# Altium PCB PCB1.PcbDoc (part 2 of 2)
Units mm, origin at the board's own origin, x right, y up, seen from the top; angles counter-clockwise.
Board outline 100 x 100 mm, 4 copper layers (Top Layer, Layer 1, Layer 2, Bottom Layer), stack 1.55 mm thick; 90 components, 49 nets, 314 pads, 474 vias.
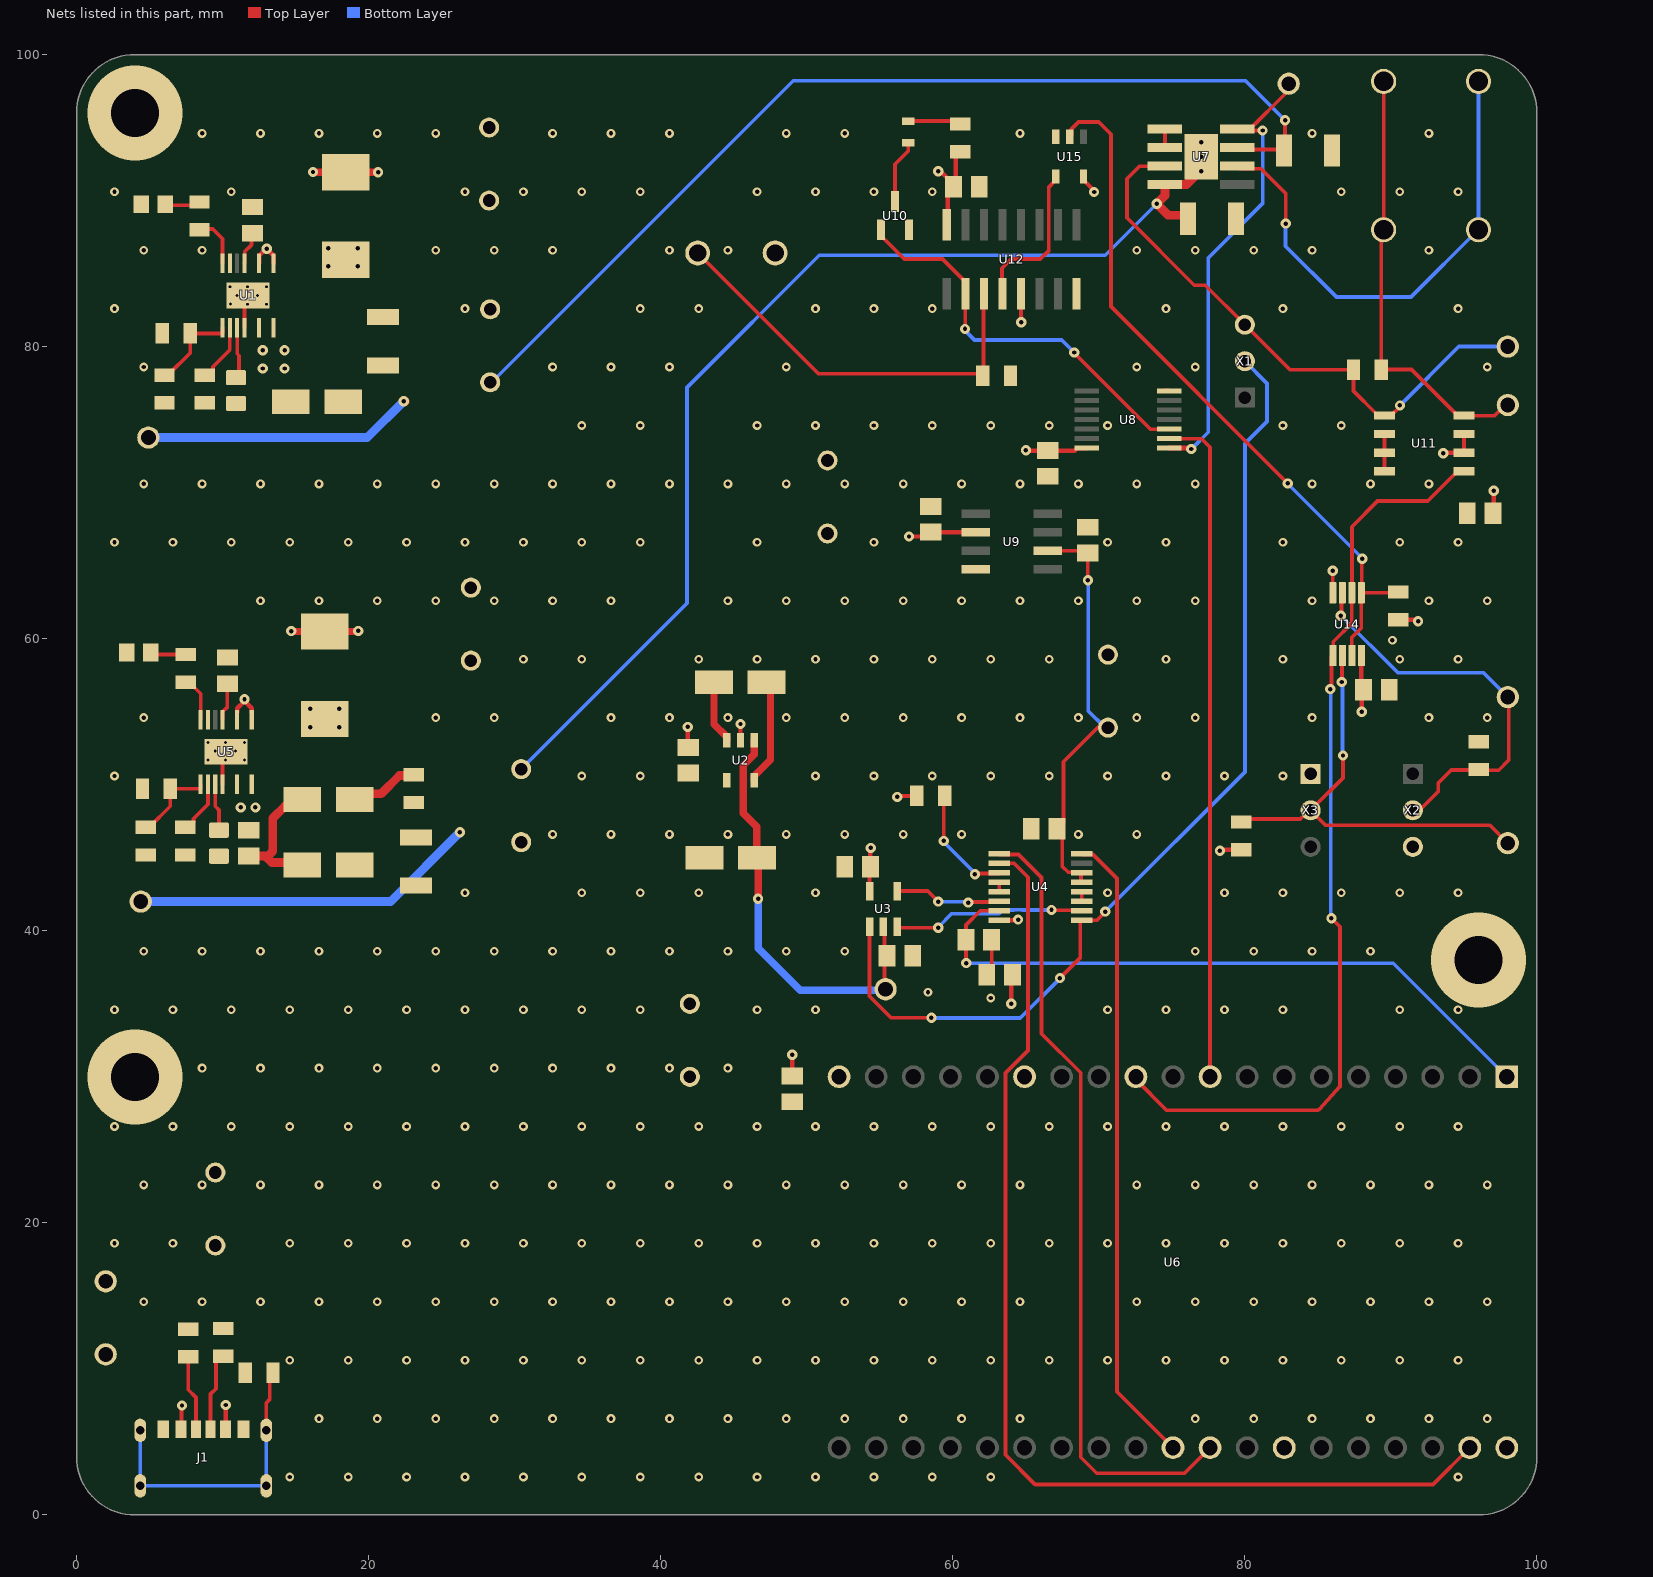
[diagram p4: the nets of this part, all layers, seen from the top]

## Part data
C1 C7 C10 C11 C17 C19 C23 C33: library part 450BXC10MEFC10X20, "No Description Available", Manufacturer_Name=Rubycon
C2 C4 J1: Package=None
CR1 CR2 CR3: "No Description Available", Manufacturer_Name="SMC Diode Solutions"
D4: "No Description Available", Manufacturer_Name="ROHM Semiconductor"
R8: library part Resistor, "Resistor"
U1 U5: library part LT8365HMSEPBF, "Low IQ Boost/SEPIC/Inverting Converter with 1.5A, 150V SwitchÂ", Manufacturer_Name="Analog Devices Inc"
U2: "Switched-Capacitor Voltage Inverters", Manufacturer_Name="Analog Devices Inc"
U3: "Zero-Drift, Single-Supply, Rail-to-Rail Input/Output Operational Amplifier", Manufacturer_Name="Analog Devices Inc"
U4: "2.7 V to 5.5 V, Serial-Input, Voltage-Output, 16-Bit nanoDACâ„¢ in 10-lead LFCSP, 16-lead 3 mm x 3 mm LFCSP, and 16-lead TSSOP", Manufacturer_Name="Analog Devices Inc"
U6: "The ESP32-DEVKITC-32UE evaluation board from Espressif Systems is designed for seamless wireless connectivity in IoT applications. Powered by the ESP32-WROOM-32UE module, it supports dual-mode BluetoothÂ® Smart Ready 4.x and 802.11 b/g/n Wi-Fi at 2.4GHz.", Package="CUSTOM-38 ESPRESSIF"
U7: "180-V, wide bandwidth (6.5 MHz), high-slew rate (25 V/Âµs) unity-gain stable op amp 8-SO PowerPAD -40 to 85", Manufacturer_Name="Texas Instruments"
U8: "4-ch, 2-input, 2-V to 6-V 5.2 mA drive strength NOR gate 14-TSSOP -40 to 85", Manufacturer_Name="Texas Instruments"
U9: "Ultraprecision, Low Noise, 2.500 V XFETÂ® Voltage References", Manufacturer_Name="Analog Devices Inc"
U10: "Description", Manufacturer_Name=onsemi
U11: "-4 to 80V, bidirectional, ultra-precise current sense amplifier with enhanced PWM rejection 8-SOIC -40 to 125", Manufacturer_Name="Texas Instruments"
U12: "CMOS Quad NOR R/S Latch with 3-State Outputs 16-SOIC -55 to 125", Manufacturer_Name="Texas Instruments"
U13: "No Description Available", Manufacturer_Name="CW Industries"
U14: "Dual high voltage, low power comparator", Package="VSSOP-8 Texas Instruments"
U15: "Single 2-V to 5.5-V inverter 5-SOT-23 -40 to 125", Manufacturer_Name="Texas Instruments"
X1 X2 X3: "No Description Available", Manufacturer_Name=Murata

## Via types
v1: diameter 0.6, hole 0.3, Top Layer to Bottom Layer, tented both sides, 383 vias
v2: diameter 0.7, hole 0.3, Top Layer to Bottom Layer, tented both sides, 72 vias
v3: diameter 0.45, hole 0.2, Top Layer to Bottom Layer, tented both sides, 16 vias
v4: diameter 6.5, hole 3.3, Top Layer to Bottom Layer, 3 vias

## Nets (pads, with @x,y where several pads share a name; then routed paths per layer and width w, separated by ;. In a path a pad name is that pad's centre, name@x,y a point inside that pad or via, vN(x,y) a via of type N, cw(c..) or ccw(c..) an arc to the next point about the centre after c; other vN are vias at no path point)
+2.5: C10.1 C12.2 C21.2 U4.5 U4.6 U9.6 | length 28.9
  Top Layer w0.254: U9.6@66.5,66.02 69.1,66.02 C21.2@69.25,65.87 v2(69.25,64) ; C12.2@67.13,47 67.578,47.448 67.578,51.578 69.936,53.936 70.6,53.936 C10.1@70.625,53.911 ; C12.2@67.5,46.876 67.5,44.41 67.904,44.005 68.789,44.005 U4.6@68.819,43.975 68.775,43.93 68.775,43.37 U4.5@68.819,43.325
  Bottom Layer w0.254: v2@69.266,63.984 69.266,55.064 70.419,53.911 C10.1@70.625,53.911
+3.3: C31.2 U4.15 U6.1 | length 45.5
  Top Layer w0.254: v2(60.926,37.786) 60.899,37.813 C31.2@60.899,39.383 60.899,40.4 61.874,41.375 U4.15@63.181,41.375
  Bottom Layer w0.254: v2(60.926,37.786) 90.158,37.786 U6.1@97.935,30.008
+5: C1.1 C9.2 C11.1 C19.1 C20.2 C22.1 C23.1 C26.1 C27.2 C28.2 C29.2 C30.2 C33.1 C34.2 J1.A9 J1.B9 L1.1 L2.1 R5.1 R13.2 R15.2 R16.2 TP+5.1 U1.1 U1.3 U2.2 U3.5 U4.16 U5.1 U5.3 U6.19 U8.14 U9.2 U11.6 U11.7 U12.5 U12.16 U13.1 U14.8 U15.5 X2.3 | length 58.9
  Top Layer w0.3: J1.B9@7.16,5.88 7.19,5.91 7.19,7.47 v2(7.22,7.5) ; J1.A9@10.2,5.88 10.212,5.892 10.212,7.524 v2(10.224,7.535) ; U5.3@11.001,54.983 11.001,55.245 11.499,55.743 v2(11.499,55.851) 11.499,55.745 12,55.244 U5.1@12,54.983 ; U1.3@12.5,85.716 12.5,86.223 12.978,86.701 v2(13.022,86.701) ; v2@13.042,86.681 13.5,86.223 U1.1@13.5,85.716 ; v2(14.703,60.519) v2@14.724,60.497 ; v2(16.191,91.952) v2@16.2,91.943 ; v2@19.256,60.497 v2(19.293,60.534) ; v2@20.648,91.943 v2(20.65,91.941) ; v2(41.846,53.96) 41.846,52.587 C22.1@41.874,52.559 ; U2.2@45.467,53.044 v2(45.465,54.163) ; v2(49.008,31.517) 49.008,30.063 C34.2@49.017,30.054 ; U3.5@54.3,42.719 54.3,44.34 C30.2@54.36,44.4 54.36,45.649 v2(54.386,45.674) ; v2(56.192,49.167) 56.259,49.234 R5.1@57.538,49.234 ; v2(57,67) 58.193,67 C20.2@58.491,67.297 58.498,67.29 U9.2@61.572,67.29 ; v2(59,92) 59.077,91.923 59.244,91.923 60.05,91.118 C28.2@60.05,90.958 ; U12.16@59.591,88.342 59.665,88.416 59.665,90.573 C28.2@60.05,90.958 ; R13.2@60.524,93.335 60.499,93.335 60.192,93.028 60.192,91.1 C28.2@60.05,90.958 ; U4.16@63.181,40.725 64.428,40.725 v2(64.472,40.768) ; v2(64,35) 64,36.92 C9.2@64.08,37 ; U12.5@64.671,83.617 64.671,81.694 v2(64.691,81.674) ; v2(65.004,72.91) 65.034,72.88 C26.1@66.5,72.88 68.35,72.88 68.52,73.05 U8.14@69.181,73.05 ; U15.5@68.95,91.638 68.95,91.405 69.674,90.682 v2(69.674,90.586) ; v2(78.288,45.481) 78.355,45.548 R16.2@79.75,45.548 ; U14.8@87.975,58.85 87.975,56.645 C27.2@88.12,56.5 88,56.38 v2(88,55) ; R15.2@90.5,61.297 91.762,61.297 v2(91.86,61.2) ; v2(93.588,72.7) 93.623,72.735 U11.6@95.003,72.735 U11.7@95.003,74.005 ; C29.2@96.98,68.6 97.039,68.659 v2(97.039,70.123)
  Top Layer w0.5: v2@14.724,60.497 L2.1@17,60.497 v2@19.256,60.497 ; v2@16.2,91.943 L1.1@18.44,91.943 v2@20.648,91.943
+90: C7.1 C8.2 C24.2 CR1.1 R3.2 TP+90.1 U7.7 | length 88.1
  Top Layer w0.254: U7.7@79.477,93.635 79.611,93.501 82.595,93.501 C24.2@82.673,93.423 82.75,93.5 v2(82.75,95.5)
  Top Layer w0.6: v2@22.435,76.229 22.449,76.242 22.492,76.242 v2@22.509,76.226
  Bottom Layer w0.254: C7.1@28.324,77.556 28.43,77.556 49.083,98.209 80.041,98.209 v2(82.75,95.5)
  Bottom Layer w0.6: TP+90.1@4.921,73.772 19.908,73.772 v2@22.398,76.261
  other v2: 22.403,76.261
-5: C2.2 C32.2 TP-5.1 U2.1 U3.2 | length 29.3
  Top Layer w0.254: U3.2@55.25,40.281 55.325,40.206 55.325,36.075 TP-5.1@55.4,36
  Top Layer w0.508: U2.1@46.417,53.044 46.417,52.078 45.663,51.324 45.663,48.043 46.585,47.121 46.585,44.841 46.67,44.756 v2(46.67,42.19)
  Bottom Layer w0.508: v2(46.67,42.19) 46.67,38.81 49.557,35.923 55.323,35.923 TP-5.1@55.4,36
-90: C17.2 C18.2 C25.1 R8.1 R9.2 TP-90.1 U7.4 U7.9 | length 99.7
  Top Layer w0.6: C25.1@75.87,89 74.742,89 v2(73.967,89.775) 74.523,90.332 U7.4@74.523,91.095 74.535,91.106 76.025,91.106 76.6,91.681 76.6,91.75 76.85,92 v2(77,92) v2(77,93)
  Bottom Layer w0.254: C17.2@30.45,51.073 41.8,62.423 41.8,77.2 50.852,86.252 70.444,86.252 v2(73.967,89.775)
  Bottom Layer w0.6: TP-90.1@4.4,42 21.5,42 v2(26.25,46.75)
  other v2: 77,94
CLK: U4.9 U6.28 | length 54.4
  Top Layer w0.254: U4.9@63.181,45.275 63.231,45.224 64.5,45.224 66.078,43.646 66.078,32.951 68.753,30.276 68.753,3.956 69.849,2.86 75.867,2.86 U6.28@77.615,4.608
CS: U4.8 U6.29 | length 43.7
  Top Layer w0.254: U4.8@68.819,45.275 68.87,45.224 69.597,45.224 71.239,43.582 71.239,8.444 U6.29@75.075,4.608
DIN: U4.10 U6.21 | length 76.2
  Top Layer w0.254: U4.10@63.181,44.625 64.189,44.625 65.149,43.666 65.149,31.808 63.609,30.268 63.609,4.119 65.637,2.091 92.877,2.091 U6.21@95.395,4.608
"Electrode +": Post2.1 U7.6 | length 34.4
  Top Layer w0.254: U7.6@79.477,92.365 79.661,92.181 81.103,92.181 82.804,90.48 v2(82.804,88.42)
  Bottom Layer w0.254: v2(82.804,88.42) 82.783,88.399 82.783,86.876 86.267,83.392 91.375,83.392 Post2.1@95.983,88 ; Post2.1@96,88 Post2.1@96,98.16
"Electrode -": E1.1 R11.1 U7.3 U11.1 X1.3 | length 40.2
  Top Layer w0.254: U7.3@74.511,92.352 72.775,92.352 71.922,91.499 71.922,88.815 76.53,84.207 77.293,84.207 X1.3@80,81.5 83.075,78.425 87.437,78.425 R11.1@87.439,78.427 87.439,76.954 88.96,75.433 88.96,75.427 89.112,75.275 U11.1@89.56,75.275 90.008,75.275 90.612,75.879 v2(90.612,75.973)
  Bottom Layer w0.254: v2(90.612,75.973) 94.639,80 E1.1@98,80
EN_OPA: U6.9 U8.2 | length 46.1
  Top Layer w0.254: U8.2@74.819,73.7 77.016,73.7 77.611,73.104 77.611,30.012 U6.9@77.615,30.008
EN_OPA2: U8.3 U10.1 U12.2 | length 27.6
  Top Layer w0.254: U10.1@55.095,88 55.095,87.568 55.247,87.416 55.261,87.416 56.677,86 59.291,86 60.861,84.43 U12.2@60.861,83.617 60.847,83.603 60.847,81.227 v2(60.834,81.213) ; v2(68.314,79.598) 68.314,79.554 73.518,74.35 U8.3@74.819,74.35
  Bottom Layer w0.254: v2(60.834,81.213) 60.834,81.109 61.491,80.452 67.46,80.452 v2(68.314,79.598)
GND: C1.2 C2.1 C3.2 C5.1 C6.1 C7.2 C8.1 C9.1 C10.2 C11.2 C12.1 C13.2 C14.1 C15.1 C17.1 C18.1 C19.2 C20.1 C21.1 C22.2 C23.2 C24.1 C25.2 C26.2 C27.1 C28.1 C29.1 C30.1 C31.1 C32.1 C33.2 C34.1 CR3.1 J1.A12 J1.B12 R2.1 R4.2 R7.1 R10.2 R12.2 R14.2 R17.1 R18.1 R19.1 TP_gnd.1 U1.7 U1.12 U1.17 U2.4 U4.3 U4.4 U4.12 U4.13 U5.7 U5.12 U5.17 U6.14 U6.20 U6.26 U7.1 U7.2 U8.7 U9.4 U10.2 U11.2 U11.3 U11.4 U12.8 U14.4 U15.3 X3.1 | length 17
  Top Layer w0.254: J1.B12@5.93,5.88 J1.B12@6,5.95 ; U5.12@10,50.034 U5.17@10,52 ; U1.17@10.75,82.751 10.899,82.9 U1.17@11.5,82.9 ; J1.A12@11.43,5.88 J1.A12@11.5,5.95 ; R12.2@11.5,9.703 R12.2@11.548,9.75 ; U1.12@11.5,81.284 U1.17@11.5,82.9 ; U1.17@11.75,83.5 11.5,83.25 U1.17@11.5,83.1 ; C2.1@43.052,45.052 C2.1@43.1,45.1 ; C28.1@61.81,90.958 C28.1@61.958,90.81 ; C9.1@62.32,37 62.659,37.339 C31.1@62.659,39.383 ; U4.13@62.571,42.677 62.573,42.675 U4.13@63.181,42.675 U4.12@63.181,43.325 ; R14.2@63.953,78 R14.2@64,77.953 ; C12.1@65.363,46.993 C12.1@65.37,47 ; U15.3@66.923,94.665 67.05,94.538 U15.3@67.05,94.362 ; U12.8@68.432,83.568 U12.8@68.481,83.617 ; U4.3@68.819,42.025 U4.4@68.819,42.675 ; C21.1@69.25,67.63 C21.1@69.295,67.585 ; U8.7@74.483,77.001 74.769,77.001 U8.7@74.819,76.95 ; U7.2@74.523,93.635 U7.1@74.523,94.905 ; v2(86.023,64.648) 86.024,64.647 86.024,63.151 U14.4@86.025,63.15 ; U11.4@89.56,71.465 U11.3@89.56,72.735 U11.2@89.56,74.005 ; C27.1@89.88,56.5 C27.1@90,56.38 ; U1.17@11.5,82.9 v3(11.7,82.9) U1.17@11.5,83.1 ; U1.17@11.5,82.9 U1.17@11.5,83.1
  Top Layer w0.508: C22.2@41.89,50.779 C22.2@41.891,50.778
  other v1: 14.6,2.6 18.6,2.6 22.6,2.6 26.6,2.6 30.6,2.6 34.6,2.6 38.6,2.6 42.6,2.6 46.6,2.6 50.6,2.6 54.6,2.6 58.6,2.6 62.6,2.6 94.6,2.6 16.6,6.6 20.6,6.6 24.6,6.6 28.6,6.6 32.6,6.6 36.6,6.6 40.6,6.6 44.6,6.6 48.6,6.6 52.6,6.6 56.6,6.6 60.6,6.6 64.6,6.6 76.6,6.6 80.6,6.6 84.6,6.6 88.6,6.6 92.6,6.6 96.6,6.6 14.6,10.6 18.6,10.6 22.6,10.6 26.6,10.6 30.6,10.6 34.6,10.6 38.6,10.6 42.6,10.6 46.6,10.6 50.6,10.6 54.6,10.6 58.6,10.6 62.6,10.6 66.6,10.6 70.6,10.6 74.6,10.6 78.6,10.6 82.6,10.6 86.6,10.6 90.6,10.6 94.6,10.6 4.6,14.6 8.6,14.6 12.6,14.6 16.6,14.6 20.6,14.6 24.6,14.6 28.6,14.6 32.6,14.6 36.6,14.6 40.6,14.6 44.6,14.6 48.6,14.6 52.6,14.6 56.6,14.6 60.6,14.6 64.6,14.6 72.6,14.6 76.6,14.6 80.6,14.6 84.6,14.6 88.6,14.6 92.6,14.6 96.6,14.6 2.6,18.6 6.6,18.6 14.6,18.6 18.6,18.6 22.6,18.6 26.6,18.6 30.6,18.6 34.6,18.6 38.6,18.6 42.6,18.6 46.6,18.6 50.6,18.6 54.6,18.6 58.6,18.6 62.6,18.6 66.6,18.6 70.6,18.6 74.6,18.6 78.6,18.6 82.6,18.6 86.6,18.6 90.6,18.6 94.6,18.6 4.6,22.6 8.6,22.6 12.6,22.6 16.6,22.6 20.6,22.6 24.6,22.6 28.6,22.6 32.6,22.6 36.6,22.6 40.6,22.6 44.6,22.6 48.6,22.6 52.6,22.6 56.6,22.6 60.6,22.6 64.6,22.6 72.6,22.6 76.6,22.6 80.6,22.6 84.6,22.6 88.6,22.6 92.6,22.6 96.6,22.6 2.6,26.6 6.6,26.6 10.6,26.6 14.6,26.6 18.6,26.6 22.6,26.6 26.6,26.6 30.6,26.6 34.6,26.6 38.6,26.6 42.6,26.6 46.6,26.6 50.6,26.6 54.6,26.6 58.6,26.6 62.6,26.6 66.6,26.6 70.6,26.6 74.6,26.6 78.6,26.6 82.6,26.6 86.6,26.6 90.6,26.6 94.6,26.6 8.6,30.6 12.6,30.6 16.6,30.6 20.6,30.6 24.6,30.6 28.6,30.6 32.6,30.6 36.6,30.6 40.6,30.6 44.6,30.6 2.6,34.6 6.6,34.6 10.6,34.6 14.6,34.6 18.6,34.6 22.6,34.6 26.6,34.6 30.6,34.6 34.6,34.6 38.6,34.6 46.6,34.6 50.6,34.6 70.6,34.6 74.6,34.6 78.6,34.6 82.6,34.6 90.6,34.6 94.6,34.6 62.6,35.4 58.3,35.8 4.6,38.6 8.6,38.6 12.6,38.6 16.6,38.6 20.6,38.6 24.6,38.6 28.6,38.6 32.6,38.6 36.6,38.6 40.6,38.6 44.6,38.6 48.6,38.6 52.6,38.6 76.6,38.6 80.6,38.6 84.6,38.6 88.6,38.6 26.6,42.6 34.6,42.6 38.6,42.6 42.6,42.6 50.6,42.6 70.6,42.6 78.6,42.6 82.6,42.6 86.6,42.6 90.6,42.6 94.6,42.6 32.6,46.6 36.6,46.6 40.6,46.6 44.6,46.6 48.6,46.6 52.6,46.6 56.6,46.6 60.6,46.6 68.6,46.6 72.6,46.6 2.6,50.6 34.6,50.6 38.6,50.6 50.6,50.6 54.6,50.6 58.6,50.6 62.6,50.6 66.6,50.6 70.6,50.6 74.6,50.6 78.6,50.6 82.6,50.6 4.6,54.6 24.6,54.6 28.6,54.6 36.6,54.6 40.6,54.6 44.6,54.6 48.6,54.6 52.6,54.6 56.6,54.6 60.6,54.6 64.6,54.6 68.6,54.6 72.6,54.6 76.6,54.6 84.6,54.6 92.6,54.6 96.6,54.6 30.6,58.6 34.6,58.6 42.6,58.6 46.6,58.6 50.6,58.6 54.6,58.6 58.6,58.6 62.6,58.6 66.6,58.6 74.6,58.6 82.6,58.6 90.6,58.6 94.6,58.6 90.1,59.9 12.6,62.6 16.6,62.6 20.6,62.6 24.6,62.6 28.6,62.6 32.6,62.6 36.6,62.6 44.6,62.6 48.6,62.6 52.6,62.6 56.6,62.6 60.6,62.6 64.6,62.6 68.6,62.6 72.6,62.6 76.6,62.6 84.6,62.6 92.6,62.6 96.6,62.6 2.6,66.6 6.6,66.6 10.6,66.6 14.6,66.6 18.6,66.6 22.6,66.6 26.6,66.6 30.6,66.6 34.6,66.6 38.6,66.6 46.6,66.6 54.6,66.6 70.6,66.6 74.6,66.6 82.6,66.6 90.6,66.6 94.6,66.6 4.6,70.6 8.6,70.6 12.6,70.6 16.6,70.6 20.6,70.6 24.6,70.6 28.6,70.6 32.6,70.6 36.6,70.6 40.6,70.6 44.6,70.6 48.6,70.6 52.6,70.6 56.6,70.6 60.6,70.6 64.6,70.6 68.6,70.6 72.6,70.6 76.6,70.6 84.6,70.6 88.6,70.6 92.6,70.6 34.6,74.6 38.6,74.6 46.6,74.6 50.6,74.6 54.6,74.6 58.6,74.6 62.6,74.6 66.6,74.6 70.6,74.6 82.6,74.6 86.6,74.6 4.6,78.6 32.6,78.6 36.6,78.6 40.6,78.6 48.6,78.6 72.6,78.6 76.6,78.6 96.6,78.6 2.6,82.6 26.6,82.6 38.6,82.6 42.6,82.6 50.6,82.6 54.6,82.6 58.6,82.6 74.6,82.6 82.6,82.6 94.6,82.6 4.6,86.6 8.6,86.6 24.6,86.6 28.6,86.6 32.6,86.6 40.6,86.6 44.6,86.6 72.6,86.6 76.6,86.6 80.6,86.6 84.6,86.6 92.6,86.6 2.6,90.6 10.6,90.6 26.6,90.6 30.6,90.6 34.6,90.6 38.6,90.6 46.6,90.6 50.6,90.6 54.6,90.6 58.6,90.6 86.6,90.6 90.6,90.6 94.6,90.6 8.6,94.6 12.6,94.6 16.6,94.6 20.6,94.6 24.6,94.6 32.6,94.6 36.6,94.6 40.6,94.6 48.6,94.6 52.6,94.6 64.6,94.6 84.6,94.6 92.6,94.6
  other v3: 9,51.7 10.2,51.7 11.5,51.7 9.5,52.3 10.9,52.3 9,52.9 10.2,52.9 11.5,52.9 13,82.9 10.536,82.922 11,83.5 12.4,83.5 10.5,84.1 11.7,84.1 13,84.1
  other v4: 4,30 96,38 4,96
INV: U3.4 U4.14 | length 7.3
  Top Layer w0.254: U3.4@56.2,42.719 58.281,42.719 v2(59,42) ; v2(61.057,41.931) 61.104,41.978 63.134,41.978 U4.14@63.181,42.025
  Bottom Layer w0.254: v2(59,42) 59.003,41.997 60.991,41.997 v2(61.057,41.931)
NetC3_1: C3.1 U1.5 | length 2.3
  Top Layer w0.254: U1.5@11.5,85.716 11.513,85.729 11.513,86.502 11.976,86.965 11.976,87.67 C3.1@12.062,87.756
NetC4_1: C4.1 U2.5 | length 7.3
  Top Layer w0.508: U2.5@46.417,50.314 46.417,50.598 47.518,51.7 47.518,56.757 C4.1@47.247,57.028
NetC4_2: C4.2 U2.3 | length 4.3
  Top Layer w0.508: C4.2@43.647,57.028 43.647,54.148 44.517,53.279 U2.3@44.517,53.044
NetC5_2: C5.2 U1.11 | length 3.5
  Top Layer w0.254: C5.2@10.922,77.88 11.126,78.084 11.126,79.378 11,79.503 U1.11@11,81.284
NetC6_2: C6.2 R1.1 | length 2.5
  Top Layer w0.254: C6.2@6.075,89.75 6.156,89.67 8.193,89.67 R1.1@8.422,89.899
NetC13_1: C13.1 U5.5 | length 2.6
  Top Layer w0.254: U5.5@10,54.466 10,54.993 10.33,55.323 C13.1@10.33,56.905
NetC14_2: C14.2 U5.11 | length 3.2
  Top Layer w0.254: U5.11@9.5,50.034 9.5,48.521 9.75,48.271 C14.2@9.75,46.888
NetC15_2: C15.2 R6.1 | length 2.4
  Top Layer w0.254: C15.2@5.094,59.049 5.222,58.921 R6.1@7.467,58.921
NetC16_1: C16.1 CR2.1 CR3.2 | length 9.4
  Top Layer w0.6: C16.1@11.807,45.126 13.122,45.126 ; CR3.2@15.447,44.5 15.271,44.676 13.364,44.676 13.018,45.022 13.122,45.126 ; CR2.1@15.447,49 14.997,48.55 14.281,48.55 13.442,47.711 13.442,45.446 13.122,45.126
NetC16_2: C16.2 L2.2 U5.14 U5.16
  other v2: 11.251,48.448 12.251,48.448 16.001,53.948 18.001,53.948 16.001,55.198 18.001,55.198
NetCR1_2: CR1.2 L1.2 U1.14 U1.16
  other v2: 12.75,78.5 14.25,78.5 12.75,79.75 14.25,79.75 17.25,85.5 19.25,85.5 17.25,86.742 19.25,86.742
NetCR2_2: CR2.2 R9.1 | length 4.7
  Top Layer w0.6: CR2.2@19.053,49 19.44,49.386 20.873,49.386 22.119,50.632 22.978,50.632 R9.1@23.059,50.713
NetD4_1: D4.1 U10.3 | length 4.4
  Top Layer w0.254: U10.3@56.042,89.935 56.042,92.484 56.949,93.39 D4.1@56.949,93.945
NetD4_2: D4.2 R13.1 | length 3.7
  Top Layer w0.254: D4.2@56.949,95.443 60.32,95.443 R13.1@60.524,95.24
NetE2_1: E2.1 Post1.1 R11.2 U11.8 | length 30.1
  Top Layer w0.254: R11.2@89.338,78.433 89.338,87.838 Post1.1@89.5,88 Post1.1@89.5,98.16 ; R11.2@89.344,78.427 91.402,78.427 94.554,75.275 U11.8@95.003,75.275 97.108,75.275 97.833,76 E2.1@98,76
NetEN_1: EN.1 U7.8 U8.1 | length 30.5
  Top Layer w0.254: U8.1@74.819,73.05 U8.1@74.844,73.025 ; v2(81.213,94.795) 81.21,94.798 80.449,94.798 80.342,94.905 82.757,97.32 82.757,97.757 EN.1@83,98
  Top Layer w0.356: U8.1@74.82,73.049 76.27,73.049 v2(76.328,72.991)
  Bottom Layer w0.254: v2(76.328,72.991) 76.349,72.991 77.488,74.13 77.488,86.072 81.213,89.797 v2(81.213,94.795)
NetJ1_A5: J1.A5 R18.2 | length 5.2
  Top Layer w0.254: R18.2@7.651,10.824 7.651,8.576 8.18,8.047 J1.A5@8.18,5.88
NetJ1_B5: J1.B5 R19.2 | length 5.4
  Top Layer w0.254: J1.B5@9.18,5.88 9.18,8.28 9.551,8.651 9.551,10.532 9.881,10.862 R19.2@10.058,10.862
NetJ1_S1: J1.S1 J1.S2 J1.S3 J1.S4 R12.1 | length 20.4
  Top Layer w0.254: J1.S2@13,5.8 13,7.679 13.224,7.902 13.224,9.521 R12.1@13.453,9.75
  Bottom Layer w0.254: J1.S1@4.36,5.8 J1.S3@4.36,2 J1.S4@13,2 J1.S2@13,5.8
NetR1_2: R1.2 U1.8 | length 3.5
  Top Layer w0.254: R1.2@8.422,87.994 8.476,88.047 9.33,88.047 10,87.377 U1.8@10,85.716
NetR2_2: R2.2 U1.10 | length 4.1
  Top Layer w0.254: R2.2@8.774,78.05 9.015,78.05 9.345,78.38 9.345,78.621 10.5,79.776 U1.10@10.5,81.284
NetR3_1: R3.1 R4.1 U1.9 | length 6.3
  Top Layer w0.254: R3.1@6.028,78.05 6.269,78.05 7.782,79.563 R4.1@7.782,80.903 9.987,80.903 10,80.916 U1.9@10,81.284
NetR5_2: R5.2 U4.11 | length 7.6
  Top Layer w0.254: v2(59.373,46.155) 59.373,48.708 R5.2@59.508,48.843 ; v2(61.514,43.875) 61.563,43.925 63.131,43.925 U4.11@63.181,43.975
  Bottom Layer w0.254: v2(59.373,46.155) 59.373,46.085 61.514,43.945 v2(61.514,43.875)
NetR6_2: R6.2 U5.8 | length 3.1
  Top Layer w0.254: R6.2@7.467,57.016 7.708,57.016 8.5,56.224 U5.8@8.5,54.466
NetR7_2: R7.2 U5.10 | length 3.7
  Top Layer w0.254: R7.2@7.436,47.098 7.677,47.098 8.007,47.429 8.007,47.67 9,48.663 U5.10@9,50.034
NetR8_2: R8.2 R10.1 U5.9 | length 5.8
  Top Layer w0.254: R8.2@4.751,47.098 4.992,47.098 6.419,48.526 R10.1@6.419,49.735 8.487,49.735 8.5,49.748 U5.9@8.5,50.034
NetR14_1: R14.1 U12.3 U13.6 | length 28.6
  Top Layer w0.254: U13.6@42.534,86.411 50.794,78.15 61.897,78.15 R14.1@62.048,78 62.095,78.047 62.095,78.241 62.095,83.581 U12.3@62.131,83.617
NetR15_1: R15.1 U14.1 U14.7 U15.2 | length 49.4
  Top Layer w0.254: U15.2@68,94.362 68.127,94.489 68.127,94.898 68.604,95.374 69.998,95.374 70.833,94.539 70.833,82.739 v2(82.937,70.635) ; U14.7@87.325,58.85 87.325,60.095 87.975,60.745 U14.1@87.975,62.602 ; U14.1@87.975,62.715 U14.1@87.975,63.15 ; v2(88.042,65.479) 88.009,65.445 88.009,63.184 U14.1@87.975,63.15 ; R15.1@90.5,63.202 90.448,63.15 U14.1@87.975,63.15
  Bottom Layer w0.254: v2(82.937,70.635) 82.937,70.609 88.042,65.505 v2(88.042,65.479)
NetU3_3: U3.3 U4.2 | length 13.2
  Top Layer w0.254: U3.3@56.2,40.281 56.269,40.212 v2(59.002,40.212) ; v2(66.755,41.428) 66.781,41.402 68.793,41.402 U4.2@68.819,41.375
  Bottom Layer w0.254: v2(59.002,40.212) 59.002,40.248 59.93,41.176 63.156,41.176 63.408,41.428 64.174,41.428 64.191,41.445 64.752,41.445 64.769,41.428 v2(66.755,41.428)
NetU6_11: U6.11 U11.5 U14.2 U14.5 | length 64.2
  Top Layer w0.254: U6.11@72.535,30.008 72.535,29.81 74.633,27.711 85.03,27.711 85.109,27.79 86.515,29.345 86.515,40.27 v2(85.924,40.861) ; v2(85.838,56.548) 85.923,56.633 85.923,58.748 U14.5@86.025,58.85 86.051,58.876 86.051,59.795 87.325,61.069 U14.2@87.325,63.15 ; U14.2@87.329,63.154 87.329,67.671 89.084,69.426 92.515,69.426 94.554,71.465 U11.5@95.003,71.465
  Bottom Layer w0.254: v2(85.838,56.548) 85.881,56.504 85.881,40.905 v2(85.924,40.861)
NetU12_4: U12.4 U15.4 | length 10.7
  Top Layer w0.254: U12.4@63.401,83.617 63.365,83.653 63.365,85.365 64,86 65.992,86 66.578,86.585 66.578,90.933 67.05,91.405 U15.4@67.05,91.638
S1: U3.1 U4.1 X1.2 | length 68.7
  Top Layer w0.254: U3.1@54.3,40.281 54.3,35.521 55.768,34.053 v2(58.535,34.053) ; v2(67.334,36.761) 68.736,38.163 68.736,40.674 68.769,40.674 U4.1@68.819,40.725 ; U4.1@69.013,40.723 69.878,40.723 70.439,41.285 v2(70.439,41.317)
  Bottom Layer w0.254: v2(58.535,34.053) 58.561,34.027 64.624,34.027 v2@67.334,36.737 ; v2(70.439,41.317) 80,50.878 80,73.357 81.52,74.877 81.52,77.48 X1.2@80,79
V_th+: R17.2 U14.3 V_th+.1 X2.2 | length 28
  Top Layer w0.254: v2(86.565,61.578) 86.62,61.633 86.62,63.095 U14.3@86.675,63.15 ; X2.2@91.5,48.25 91.714,48.464 92.164,48.464 93.24,49.54 93.24,50.124 94.127,51.011 95.964,51.011 R17.2@96,51.048 ; R17.2@96,51 97.374,51 98.065,51.691 98.065,55.935 V_th+.1@98,56
  Bottom Layer w0.254: v2(86.565,61.578) 90.475,57.668 96.332,57.668 V_th+.1@98,56
V_th-: R16.1 U14.6 V_th-.1 X3.2 | length 31.1
  Top Layer w0.254: R16.1@79.75,47.453 79.956,47.658 83.793,47.658 84.385,48.25 X3.2@84.5,48.25 ; v2(86.626,57.032) 86.65,57.057 86.65,58.825 U14.6@86.675,58.85 ; v2(86.719,52.004) 86.719,50.469 X3.2@84.5,48.25 ; V_th-.1@98,46 96.773,47.227 85.523,47.227 X3.2@84.5,48.25
  Bottom Layer w0.254: v2(86.626,57.032) 86.688,56.97 86.688,52.035 v2(86.719,52.004)
pads on no net: U1.6 U4.7 U5.6 U6.2 U6.3 U6.4 U6.5 U6.6 U6.7 U6.8 U6.10 U6.12 U6.13 U6.15 U6.16 U6.17 U6.18 U6.22 U6.23 U6.24 U6.25 U6.27 U6.30 U6.31 U6.32 U6.33 U6.34 U6.35 U6.36 U6.37 U6.38 U7.5 U8.4 U8.5 U8.6 U8.8 U8.9 U8.10 U8.11 U8.12 U8.13 U9.1 U9.3 U9.5 U9.7 U9.8 U12.1 U12.6 U12.7 U12.9 U12.10 U12.11 U12.12 U12.13 U12.14 U12.15 U15.1 X1.1 X2.1 X3.3

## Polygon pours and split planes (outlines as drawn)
GND on Bottom Layer "GND_L04_P018" (solid, pour order 18): 4,99 1,96 1,4 4,1 96,1 99,4 99,96 96,99
NetC16_2 on Bottom Layer "NETC16_2_L04_P005" (solid, pour order 5): 15.5,56 15.5,50.382 14.137,49.341 15.5,49.341 10.5,49.341 10.5,47.514 19,47.514 19,52.5 19,56
NetCR1_2 on Bottom Layer "NETCR1_2_L04_P006" (solid, pour order 6): 16.75,87.5 16.75,81.673 15.245,80.487 12,80.487 12,77.5 14.5,77.5 20,77.5 20,83 20,87.5
-90 on Bottom Layer "-90_L04_P007" (solid, pour order 7): 61,98 61,87 81,87 81,98
no net on Bottom Layer "NONET_L04_P014" (solid, pour order 14): 80.5,91.625 80.5,91.62
GND on Top Layer "GND_L01_P019" (solid, pour order 19): 4,99 1,96 1,4 4,1 96,1 99,4 99,96 96,99
GND on Top Layer "GND_L01_P011" (solid, pour order 11): 12.975,89 12.975,92 1.75,92 1.75,69.5 11.75,69.5 11.75,76.5 7.25,76.5 7.25,73.5 6.75,73.5 6.75,79.5 6.75,81.5 6.75,82.5 14.25,82.5 14.25,81 30.25,81 30.25,84.5 15.25,84.5 12.975,84.5
GND on Top Layer "GND_L01_P009" (solid, pour order 9): 11.5,62.25 1,62.25 1,37.75 25.55,37.75 33.5,45.7 33.5,47.6 30.35,47.6 27.25,44.5 21.25,44.5 21,44.75 17.25,44.75 10.25,44.75 10.25,45.5 7,45.5 7,39.25 1.75,39.25 1.75,46 5.25,46 5.25,51 11.75,51 11.75,53.5 11.5,53.5 11.5,57.75
NetCR1_2 on Top Layer "NETCR1_2_L01_P015" (solid, pour order 15): 12.25,82 12.25,74.5 14.75,74.5 14.75,82
+90 on Top Layer "+90_L01_P012" (solid, pour order 12): 29.75,80 29.75,74 16.75,74 16.75,80
-90 on Top Layer "-90_L01_P017" (solid, pour order 17): 21.5,49.5 24.676,49.5 27,53 33.5,53 33.5,48.1 30.281,48.1 27.461,45.25 21.5,45.25
+90 on Top Layer "+90_L01_P010" (solid, pour order 10): 6.75,76.5 6.75,72.5 3.25,72.5 3.25,76.5
-90 on Top Layer "-90_L01_P008" (solid, pour order 8): 2.5,45.75 6.25,45.75 6.25,40 2.5,40
NetC16_2 on Top Layer "NETC16_2_L01_P016" (solid, pour order 16): 10.75,50.7 10.75,45.993 12.993,45.993 13,46 12.991,46.009 12.991,50.707
GND on Layer 1 "GND_L02_P000" (solid, pour order 0): 4,100 0,96 0,4 4,0 96,0 100,4 100,96 96,100
+5 on Layer 2 "+5_L03_P020" (solid, pour order 20): 5,99 1,95 1,4 4,1 96,1 99,4 99,96 96,99

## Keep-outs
Keep-Out Layer:
  the board outline again, w0.254

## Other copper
Top Layer:
  pour cut-out: 29.387,80.87 29.517,81 30.45,81 30.45,79.025 30.351,78.927 30.006,79.272 30.006,80.165
  pour cut-out: 13.04,59.389 12.548,58.897 12.46,58.897 12.46,54.443 11.9,53.883 11.9,51.52 12.573,50.846 13.066,50.846 13.066,50.72 13.772,50.013 13.848,50.089 20.877,50.089 22.353,51.565 22.2,51.718 22.2,59.807 21.974,60.033 18.757,60.033 18.757,58.72 18.643,58.607 18.504,58.746 13.987,58.746
  pour cut-out: 14.148,47.716 21.158,47.716 21.195,47.752 21.279,47.667 21.279,44.829 20.685,44.829 20.443,45.072 20.443,45.484 14.116,45.484 14.1,45.5
  pour cut-out: 9.174,48.492 9.109,48.492 8.215,47.598 8.215,45.591 8.967,45.591 9.163,45.787 10.494,45.787 10.494,46.169 10.603,46.278 10.603,47.772
  pour cut-out: 7.906,49.533 7.893,49.52 6.95,49.52 6.95,49.01 6.963,48.996 6.885,48.918 6.636,48.918 6.636,48.407 5.563,47.334 5.563,46.287 5.55,46.274 5.694,46.13 6.636,46.13 6.636,47.556 6.728,47.648 7.762,47.648 7.762,47.74 8.783,48.761 8.717,48.826 8.717,49.219 8.351,49.219 8.272,49.298 8.272,49.481
  pour cut-out: 14.373,90.675 13.95,90.252 13.95,85.623 13.97,85.603 13.759,85.391 13.759,84.626 13.789,84.596 16.396,84.596 16.396,87.082 14.705,88.773 14.705,90.433 14.594,90.433 14.383,90.644
  pour cut-out: 8.361,80.684 8.361,80.145 8.295,80.079 8.278,80.096 8.058,80.096 8.058,79.519 6.805,78.265 6.805,77.15 6.904,77.051 7.157,77.051 7.157,76.682 7.234,76.605 7.932,76.605 7.932,78.491 8.031,78.59 9.075,78.59 9.075,78.727 10.295,79.947 10.295,80.524 9.746,80.524 9.74,80.519 9.724,80.535 9.724,80.684
  pour cut-out: 15.144,80.876 15.144,77.549 15.195,77.498 16.568,77.498 16.568,80.23 16.982,80.644 17.076,80.644 17.076,80.862 17.04,80.898
  pour cut-out: 6.884,82.403 6.877,82.396 6.877,81.758 8.232,81.758 8.362,81.628 8.362,81.101 9.801,81.101 9.814,81.087 9.814,82.357

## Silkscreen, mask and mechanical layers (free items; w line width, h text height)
Top Overlay:
  drawing of 20 lines, arcs and shapes, not listed
  text "Alimentez le circuit avec une batterie externe pour cellulaire." at 16,2 h1
Bottom Overlay:
  text "Jeremie Beaupre" at 42.746,18.762 h1.52
  text "2026 - Electrostimulator V1" at 50.496,15.754 h1.52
